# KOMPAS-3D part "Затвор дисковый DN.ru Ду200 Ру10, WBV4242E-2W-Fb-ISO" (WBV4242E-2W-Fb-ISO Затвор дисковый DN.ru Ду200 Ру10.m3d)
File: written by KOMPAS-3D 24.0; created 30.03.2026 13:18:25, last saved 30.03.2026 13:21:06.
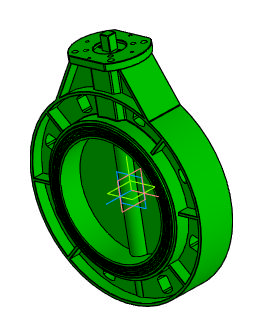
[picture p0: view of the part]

Document properties: Автор: R2D2; Полное имя файла: WBV4242E-2W-Fb-ISO Затвор дисковый DN.ru Ду200 Ру10.cdw

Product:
- Part/product: Затвор дисковый DN.ru Ду200 Ру10  | designation WBV4242E-2W-Fb-ISO
    Масса: 6.9
    Раздел спецификации: Прочие изделия
    Форматы листов документа: A2
    Примечание: D050-81210

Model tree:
1. Операция без истории:1

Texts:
  WBV4242E-2W-Fb-ISO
